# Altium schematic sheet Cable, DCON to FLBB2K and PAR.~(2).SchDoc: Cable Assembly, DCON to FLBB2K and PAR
size B; Organization: Monterey Bay Aquarium Research Institute; Address1: 7700 Sandholdt Rd; Address2: Moss Landing, CA 95039-9644; Revision: Initial; SheetNumber: 1; SheetTotal: 1; ApprovedBy: Hans Thomas; CheckedBy: Hans Thomas; CompanyName: MBARI; Engineer: Hans Thomas
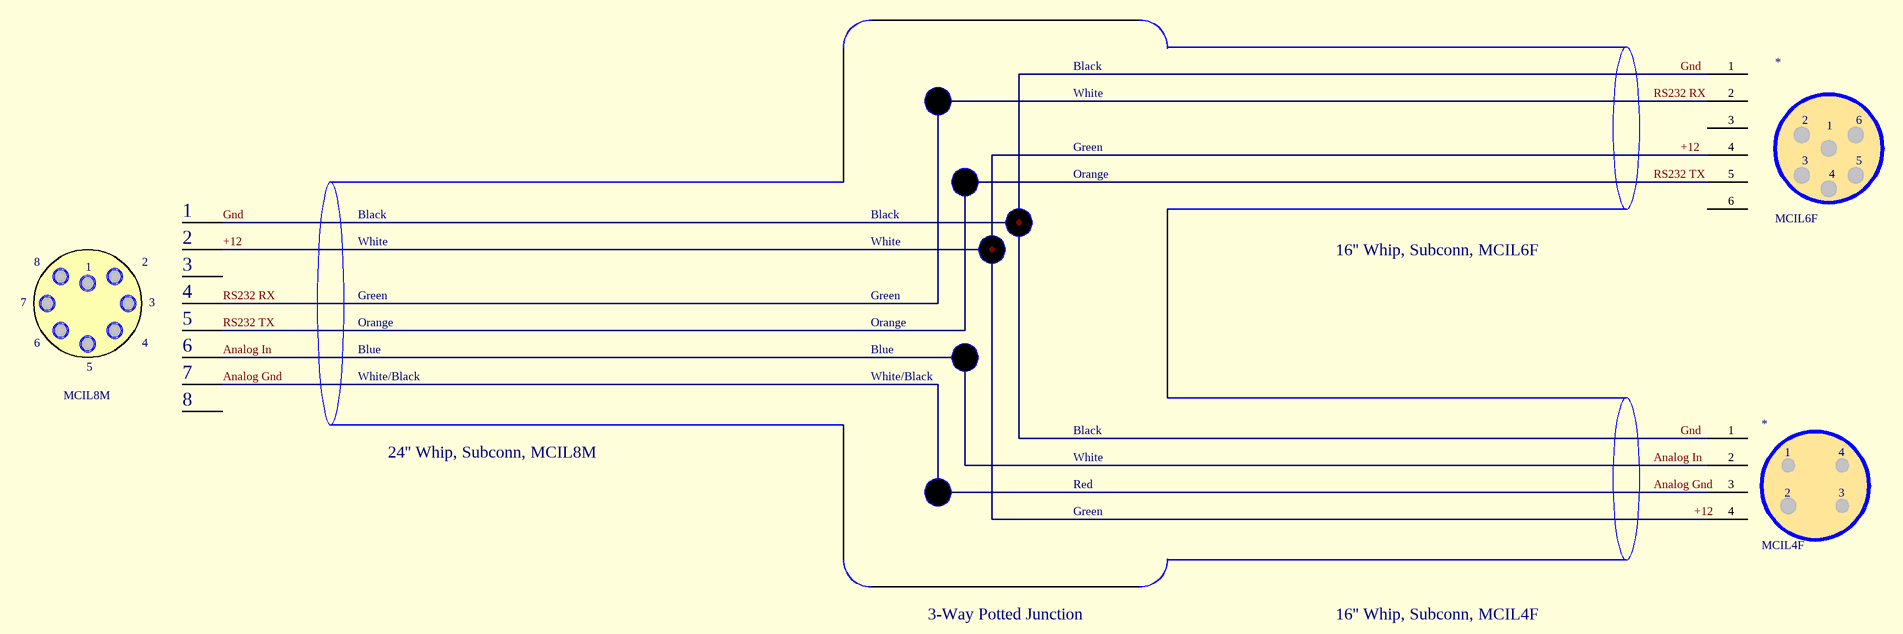
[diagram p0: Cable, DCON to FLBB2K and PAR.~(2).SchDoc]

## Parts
(Parts that share a designator on the sheet are numbered #1, #2 ... from top to bottom, then left to right.)
*#1  (no value)
*#2  MCIL8M
*#3  MCIL4F

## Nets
+12: *#1.4 *#2.2 *#3.4
Analog Gnd: *#2.7 *#3.3
Analog In: *#2.6 *#3.2
Gnd: *#1.1 *#2.1 *#3.1
RS232 RX: *#1.2 *#2.4
RS232 TX: *#1.5 *#2.5

Not connected (* = marked no-connect by the designer): *#1 3 6; *#2 3 8

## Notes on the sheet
- Black
- White
- Green
- Orange
- 16'' Whip, Subconn, MCIL6F
- Blue
- White/Black
- 24'' Whip, Subconn, MCIL8M
- Red
- 3-Way Potted Junction
- 16'' Whip, Subconn, MCIL4F

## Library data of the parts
*#1 = MCIL6F
*#2 = MCIL8M: Subconn MCIL8M pigtail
